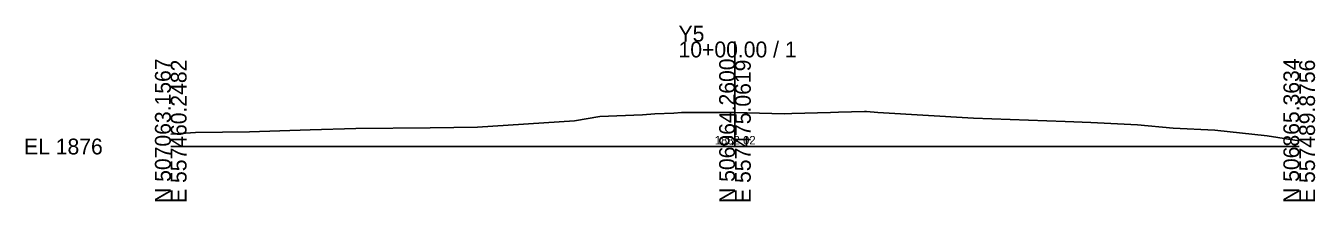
# Model space of a CAD drawing. Extents: x -26 to 1503, y -10 to 2043.
# Drawn here: x -25.7 to 202.8, y -9.7 to 21.4 of the extents above; entities that cross this region are included whole.
import ezdxf

# ---------------------------------------------------------------- set-up
doc = ezdxf.new("R2010")
doc.units = 0
for name, color, linetype in [('Default', 7, 'Continuous'), ('Exist Cross Section Cell', 7, 'Continuous'), ('Exist XS Center Line Elevation Label', 7, 'Continuous'), ('Exist XS Ground Line', 7, 'Continuous')]:
    doc.layers.add(name, color=color, linetype=linetype)

msp = doc.modelspace()

# ---------------------------------------------------------------- linework, layer by layer
at = {"layer": 'Exist Cross Section Cell'}
for p, q in [((100, 0), (100, 18.6)), ((0, 0), (100, 0)), ((100, 0), (200, 0))]:
    msp.add_line(p, q, dxfattribs=at)
at = {"layer": 'Exist XS Ground Line'}
for p, q in [((71.57, 4.54), (76.07, 5.31)), ((76.07, 5.31), (83.64, 5.64)), ((83.64, 5.64), (85.81, 5.77)), ((85.81, 5.77), (89.16, 5.94)), ((89.16, 5.94), (90.51, 6.04)), ((90.51, 6.04), (90.99, 6.04)), ((90.99, 6.04), (99.41, 6.03)), ((99.41, 6.03), (100, 6.02)), ((100, 6.02), (108.72, 5.79)), ((108.72, 5.79), (110.07, 5.86)), ((110.07, 5.86), (116.92, 6.06)), ((116.92, 6.06), (118.33, 6.07)), ((118.33, 6.07), (122.97, 6.2)), ((122.97, 6.2), (123.29, 6.2)), ((123.29, 6.2), (125.33, 6.03)), ((125.33, 6.03), (142.27, 5.01)), ((142.27, 5.01), (158.52, 4.42)), ((0, 2.22), (4.37, 2.46)), ((4.37, 2.46), (13.95, 2.59)), ((13.95, 2.59), (24.73, 2.97)), ((24.73, 2.97), (32.8, 3.18)), ((32.8, 3.18), (45.96, 3.29)), ((45.96, 3.29), (54.36, 3.45)), ((54.36, 3.45), (71.57, 4.54)), ((158.52, 4.42), (163.09, 4.25)), ((163.09, 4.25), (171.36, 3.86)), ((171.36, 3.86), (177.65, 3.23)), ((177.65, 3.23), (185.06, 2.91)), ((185.06, 2.91), (194.32, 1.88)), ((194.32, 1.88), (200, 0.99))]:
    msp.add_line(p, q, dxfattribs=at)

# ---------------------------------------------------------------- texts
at = {"layer": 'Default'}
msp.add_text('-', height=0.0001, dxfattribs=at).set_placement((0, 0))
at = {"layer": 'Exist Cross Section Cell'}
for s, p in [('Y5', (90, 18.6)), ('10+00.00 / 1', (90, 15.8)), ('EL 1876', (-26, -1.4))]:
    msp.add_text(s, height=2.8, dxfattribs=at).set_placement(p)
for s, p in [('N 507063.1567', (0, -10)), ('E 557460.2482', (2.8, -10)), ('N 506964.2600', (100, -10)), ('E 557475.0619', (102.8, -10)), ('N 506865.3634', (200, -10)), ('E 557489.8756', (202.8, -10))]:
    msp.add_text(s, height=2.8, rotation=90, dxfattribs=at).set_placement(p)
at = {"layer": 'Exist XS Center Line Elevation Label'}
msp.add_text('1882.02', height=1.5, dxfattribs=at).set_placement((96.41, 0.37))

doc.saveas('drawing.dxf')
